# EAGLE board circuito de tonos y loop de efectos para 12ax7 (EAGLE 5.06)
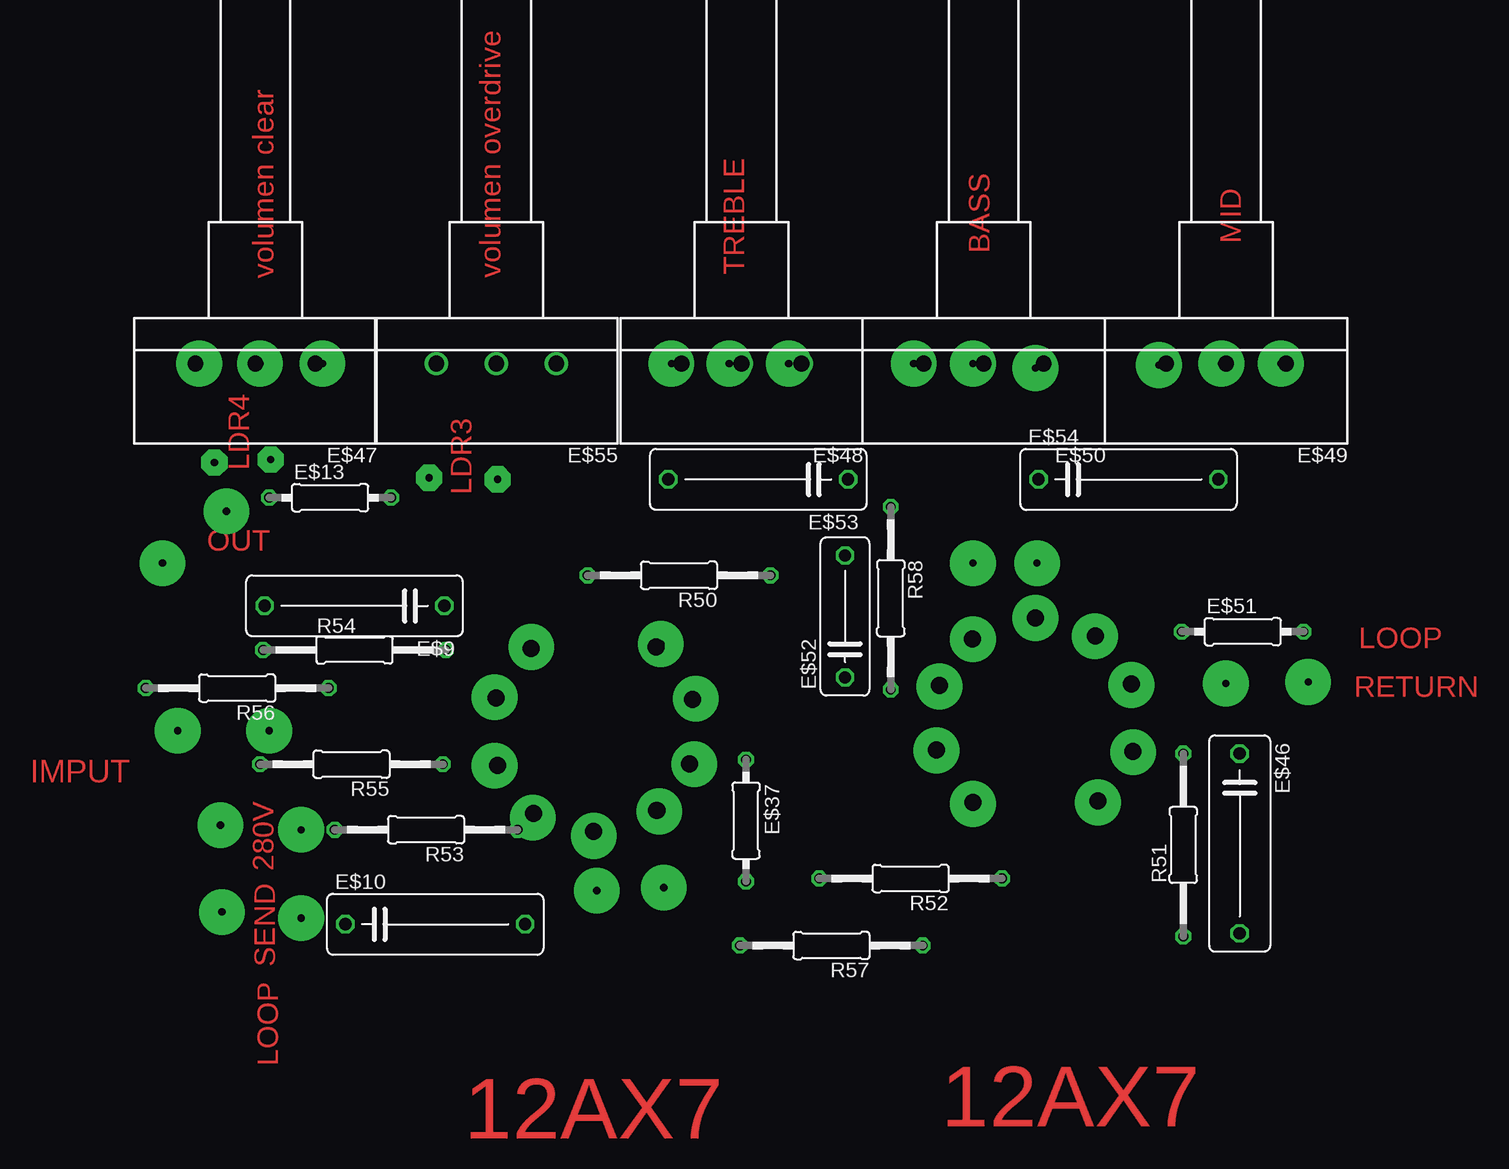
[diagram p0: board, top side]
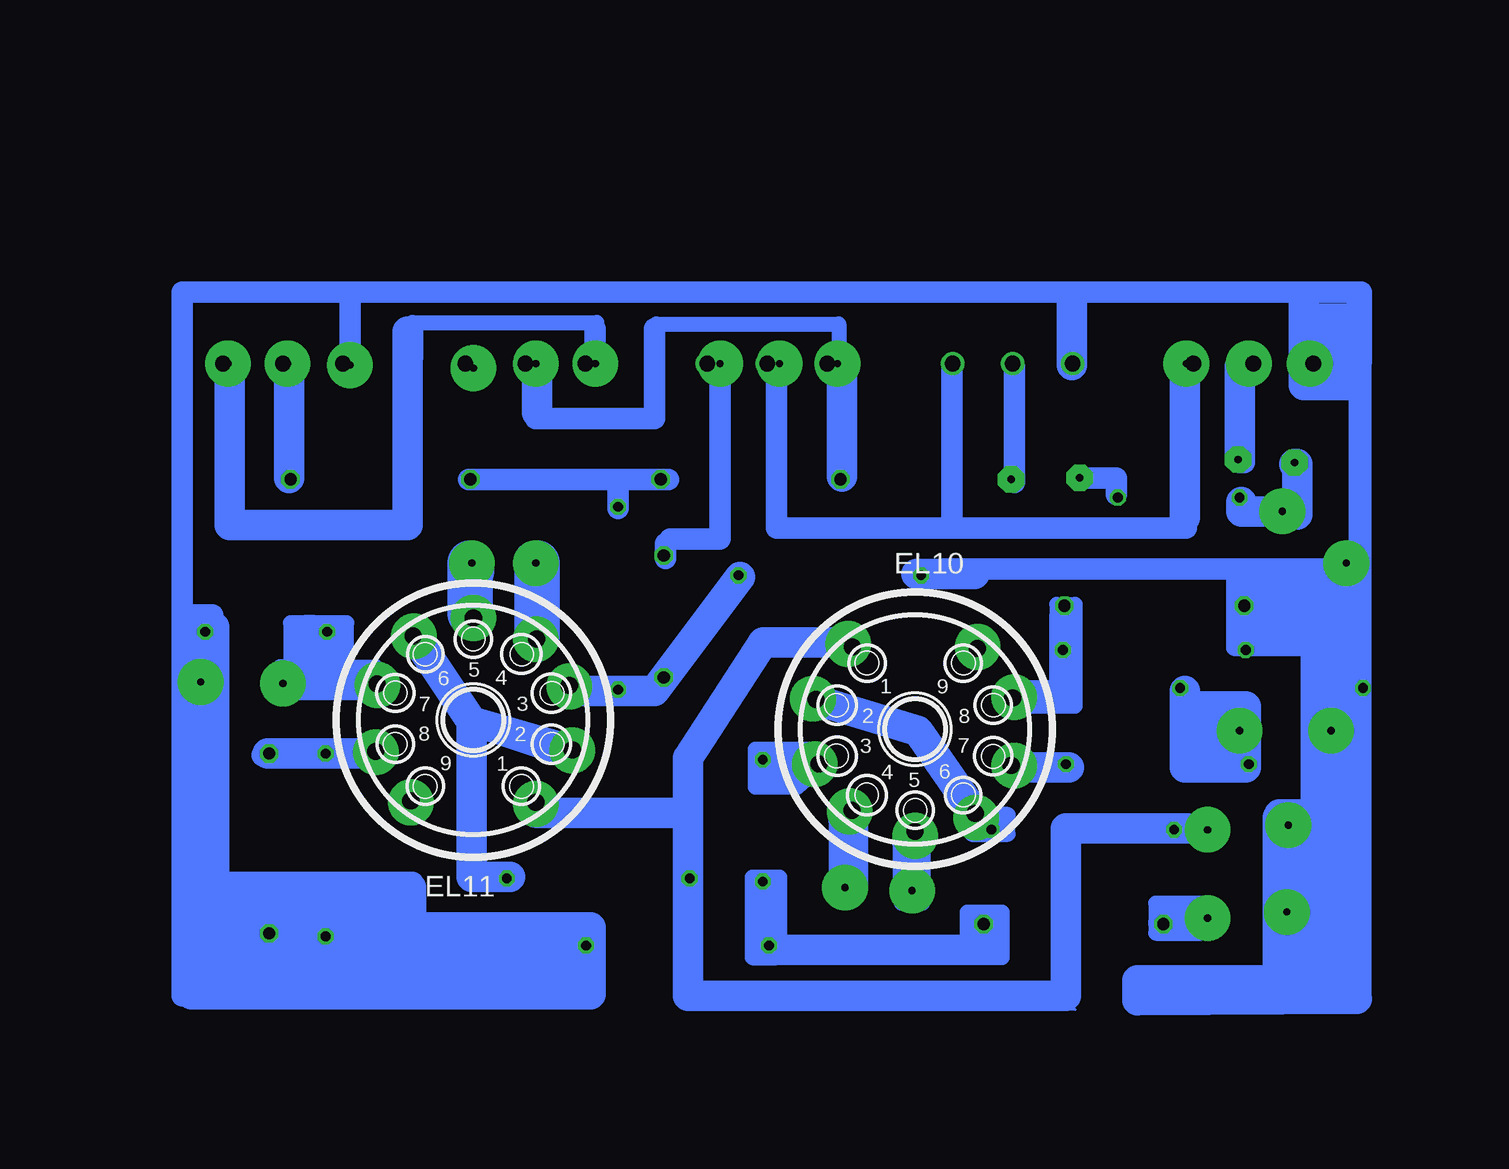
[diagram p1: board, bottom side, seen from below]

No outline drawn. Coordinates in mm, seen from the top.
Copper layers (1*16): Top 0.035mm / dielectric 1.5mm / Bottom 0.035mm
Design rules "default": minimum track width 10mil, minimum drill 24mil, track to track 8mil, track to pad 8mil, pad to pad 8mil, via to via 8mil, smd to smd 8mil, copper to edge 40mil, drill to drill 8mil, minimum pad ring 10mil, minimum via ring 8mil, stop-mask expansion 4mil, vias tented up to drill 0mil, thermal gap 10mil

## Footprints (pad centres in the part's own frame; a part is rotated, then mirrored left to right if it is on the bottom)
C150-054X183 = drill 1.016 octagon: 1 -7.493,0; 2 7.493,0
0207/10 = drill 0.813 octagon: 1 -5.08,0; 2 5.08,0
CIP20C-6MM = drill 1.3 pad 1.93 round: A -5,0; E 5,0; S 0,0
C102-043X133 = drill 1.016 octagon: 1 -5.08,0; 2 5.08,0
NOVAL = drill 1.422 pad 2.54 round: 1 5.207,-6.858; 2 8.254,-2.484; 3 8.004,2.893; 4 5.258,6.77; 5 0,8.524; 6 -5.004,7.024; 7 -8.004,3.02; 8 -8.127,-2.611; 9 -5.207,-6.731
0207/15 = drill 0.813 octagon: 1 -7.62,0; 2 7.62,0

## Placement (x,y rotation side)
E$9  1UF  [C150-054X183]  -92.84,-323.98 180 top
E$10  1UF  [C150-054X183]  -86.11,-350.52 0 top
E$13  PUENTE  [0207/10]  -94.87,-314.96 0 top
E$37  100K  [0207/10]  -60.2,-341.88 270 top
E$46  1UF  [C150-054X183]  -19.05,-343.79 270 top
E$47  1M  [CIP20C-6MM]  -101.09,-303.78 180 top
E$48  250K  [CIP20C-6MM]  -60.58,-303.78 180 top
E$49  25K  [CIP20C-6MM]  -20.19,-303.78 180 top
E$50  1M  [CIP20C-6MM]  -40.39,-303.78 180 top
E$51  1M  [0207/10]  -18.8,-326.14 0 top
E$52  470PF  [C102-043X133]  -51.94,-324.87 90 top
E$53  22NF  [C150-054X183]  -59.18,-313.44 180 top
E$54  22NF  [C150-054X183]  -28.32,-313.44 0 top
E$55  1M  [CIP20C-6MM]  -81.03,-303.78 180 top
EL10  [NOVAL]  -72.9,-334.26 180 bottom
EL11  [NOVAL]  -36.07,-333.5 0 bottom
R50  100K  [0207/15]  -65.79,-321.44 180 top
R51  2K2  [0207/15]  -23.75,-343.92 90 top
R52  220K  [0207/15]  -46.48,-346.71 180 top
R53  220K  [0207/15]  -86.87,-342.65 180 top
R54  1K8  [0207/15]  -92.84,-327.66 0 top
R55  220K  [0207/15]  -93.09,-337.19 180 top
R56  330K  [0207/15]  -102.62,-330.83 180 top
R57  2K2  [0207/15]  -53.09,-352.3 180 top
R58  47K  [0207/15]  -48.13,-323.34 270 top

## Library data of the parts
E$9 E$10 E$13 E$37 E$46 E$51-E$54 = rcl
E$47-E$50 E$55 = pot
EL10 EL11 = Tubes
R50-R58 = m-pad-2.1

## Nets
S$383: E$9.2

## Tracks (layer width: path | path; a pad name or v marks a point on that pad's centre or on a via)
S$1
  Bottom 1.778: -89.66,-314.71 -89.66,-313.31 -86.49,-313.31
S$2  (via drill 0.6 pad 3.81)
  Bottom 2.54: -41.4,-326.52 -41.27,-326.64
  Bottom 3.81: -41.4,-326.52 -41.4,-320.42 v-41.27,-320.42
S$3
  Bottom 2.54: -29.59,-352.17 -30.99,-352.17
S$4
  Bottom 2.54: -30.86,-347.47 -30.86,-350.01
S$9
  Bottom 2.54: -104.52,-312.17 -104.78,-312.17 -104.78,-316.36 -103,-316.36
S$10
  Bottom 2.54: -102.87,-316.1 -100.08,-316.1 -100.08,-315.34
S$11
  Bottom 2.54: -41.4,-303.78 -41.4,-307.85
S$12
  Bottom 2.54: -99.95,-304.04 -99.95,-311.66
S$13
  Bottom 0.406: -106.17,-298.96 -109.09,-298.96 -109.09,-298.7
S$164
  Bottom 1.676: -36.45,-320.68 -36.45,-324.99
S$334
  Bottom 2.54: -36.07,-325.12 -35.94,-325.12 -35.94,-324.99 -35.81,-324.87
S$335
  Bottom 2.54: -41.4,-320.8 -41.4,-326.9
S$336  (via drill 0.6 pad 3.81)
  other vias: -44.07,-330.71
S$337  (via drill 0.6 pad 3.81)
  other vias: -72.9,-343.15
S$338  (via drill 0.6 pad 3.81)
  other vias: -81.15,-337.31
S$339  (via drill 0.6 pad 3.81)
  other vias: -67.44,-341.12
S$340  (via drill 0.6 pad 3.81)
  other vias: -81.15,-331.6
S$341  (via drill 0.6 pad 3.81)
  other vias: -67.31,-327.15
S$342  (via drill 0.6 pad 3.81)
  other vias: -64.39,-331.72
S$343  (via drill 0.6 pad 3.81)
  other vias: -77.98,-341.63
S$344  (via drill 0.6 pad 3.81)
  other vias: -67.06,-347.47
S$345  (via drill 0.6 pad 3.81)
  other vias: -41.27,-340.49
S$346  (via drill 0.6 pad 3.81)
  Bottom 1.93: -36.07,-333.88 -36.07,-346.58 | -36.07,-333.88 -43.69,-336.42 | -30.99,-326.26 -31.24,-326.64 -36.07,-333.88
  Bottom 2.54: -35.94,-333.63 v-44.32,-336.04 | -31.24,-326.64 -35.94,-333.63 | -35.94,-333.63 -35.94,-346.58 -39.12,-346.58
S$347  (via drill 0.6 pad 3.81)
  other vias: -41.27,-326.77
S$348  (via drill 0.6 pad 3.81)
  other vias: -36.07,-324.99
S$349  (via drill 0.6 pad 3.81)
  other vias: -31.11,-326.52
S$350  (via drill 0.6 pad 3.81)
  other vias: -28.07,-330.58
S$351  (via drill 0.6 pad 3.81)
  other vias: -27.94,-336.17
S$352  (via drill 0.6 pad 3.81)
  Bottom 1.676: v-30.86,-340.36 -31.37,-340.36
S$353
  Bottom 1.93: -18.54,-336.42 -27.18,-336.42
S$354
  Bottom 1.93: -17.02,-351.66 -22.73,-351.66 | -22.73,-351.66 -23.37,-351.66 | -17.02,-351.66 -17.02,-354.2 -14.48,-354.2 | -17.02,-351.66 -13.21,-351.66 -13.21,-352.93 -15.75,-352.93 | -22.73,-351.66 -25.4,-351.66 -25.27,-356.62
S$355
  Bottom 1.93: -13.21,-347.09 -30.99,-347.09
S$356  (via drill 0.6 pad 3.81)
  other vias: -78.11,-327.41
S$357
  Bottom 2.54: -12.57,-325.25 -12.57,-355.22 | -45.85,-350.77 -45.85,-356.36 -12.57,-356.36 -12.57,-355.22 | -12.57,-355.22 -12.57,-354.08 -43.94,-354.08 -43.94,-352.68 -43.81,-352.68 -43.81,-352.3 -15.62,-352.3
S$358  (via drill 0.6 pad 3.81)
  other vias: -97.28,-342.65
S$359  (via drill 0.6 pad 3.81)
  other vias: -20.19,-330.45
S$360  (via drill 0.6 pad 3.81)
  other vias: -13.34,-330.33
S$361
  Bottom 2.54: -81.03,-337.44 -85.72,-337.44
S$362
  Bottom 2.54: -72.77,-343.03 -72.77,-347.6
S$363
  Bottom 2.54: -67.31,-341.12 -67.31,-347.47
S$366
  Bottom 2.54: -18.92,-336.3 -27.94,-336.3
S$367
  Bottom 2.54: -13.72,-349.12 -30.61,-349.12
S$368  (via drill 0.6 pad 3.81)
  other vias: -35.94,-320.42
S$369
  Bottom 3.81: -35.81,-324.61 -35.81,-320.42 -35.94,-321.06
S$370  (via drill 0.6 pad 3.81)
  other vias: -72.64,-347.73
S$371  (via drill 0.6 pad 3.81)
  other vias: -64.52,-337.19
S$372  (via drill 0.6 pad 3.81)
  other vias: -97.28,-350.01
S$373
  Bottom 2.54: -78.61,-350.39 -78.49,-352.68 -60.45,-352.68 -60.45,-347.35
S$374
  Bottom 2.54: -95.63,-342.52 -85.47,-342.52 -85.47,-356.49 -53.98,-356.49 -53.98,-341.25
S$375
  Bottom 2.54: -64.52,-336.93 -60.33,-336.93 -60.33,-338.45
S$376
  Bottom 1.93: -41.15,-340.23 -41.15,-341.5
S$377
  Bottom 2.54: -41.4,-341.25 -53.47,-341.25
S$378
  Bottom 2.54: -45.59,-350.77 -13.34,-350.77 -13.34,-350.65
S$379
  Bottom 2.54: -93.6,-350.39 -97.28,-350.14
S$380
  Bottom 2.54: -77.98,-341.38 -73.15,-334.39 -63.88,-331.6
S$381
  Bottom 2.54: -97.92,-334.77 -97.92,-337.19
S$382
  Bottom 2.54: -85.34,-324.87 -85.34,-331.6 -81.03,-331.6
S$383
  Bottom 2.54: -100.58,-326.26 -100.58,-322.71 E$9.2 -100.33,-325.12 -109.35,-325.12
S$384
  Bottom 1.778: -52.07,-318.77 -52.07,-320.04
S$385
  Bottom 2.54: -67.31,-327.02 -60.2,-327.02 -53.98,-336.68 -53.98,-344.68
S$386
  Bottom 2.54: -44.07,-331.34 -43.94,-331.22
S$387
  Bottom 2.54: -28.19,-330.58 -23.37,-330.45 -20.07,-330.45
S$388
  Bottom 1.93: -109.98,-303.28 -109.98,-356.74
S$389
  Bottom 2.54: -103.12,-341.63 -103.12,-356.49
S$390
  Bottom 2.54: -103.25,-341.38 -109.35,-341.38
S$391
  Bottom 2.54: -106.3,-326.77 -109.47,-326.77 | -100.46,-326.77 -106.3,-326.77 | -109.22,-356.36 -103.25,-356.36 -103.25,-356.49 -104.9,-356.49 -104.9,-342.65 -106.68,-342.65 | -106.68,-342.65 -108.2,-342.65 -108.2,-342.9 -108.08,-342.9 -108.08,-354.84 -106.55,-354.84 | -106.55,-354.84 -106.17,-354.84 | -106.55,-354.84 -106.55,-344.3 | -106.3,-326.77 -106.3,-342.65 -106.68,-342.65
S$392
  Bottom 0.254: -109.35,-356.87 -109.35,-357.63
S$393
  Bottom 0.254: -86.23,-357.63 -85.6,-357.63
S$394
  Bottom 2.54: -109.73,-356.74 -91.44,-356.87 -91.44,-355.22 -101.98,-355.22
S$395
  Bottom 2.54: -108.33,-327.28 -108.33,-342.77 -108.58,-342.77
S$396
  Bottom 2.54: -14.48,-325.75 -14.48,-353.19 -13.84,-353.19
S$397
  Bottom 2.54: -73.03,-321.31 -77.85,-321.31
S$398
  Bottom 1.778: -25.78,-297.81 -11.81,-297.81 -11.81,-324.74 | -25.78,-297.81 -110.11,-297.81 -110.11,-303.66 -105.79,-303.66 | -11.81,-324.74 -11.81,-356.49 | -25.78,-297.81 -25.78,-304.42 | -11.81,-324.74 -14.35,-324.74
S$399
  Bottom 1.778: -23.24,-326.01 -24.51,-326.01 -24.51,-329.82
S$400
  Bottom 1.778: -100.84,-303.78 -100.33,-303.78 -100.33,-312.04
S$401
  Bottom 1.778: -95.63,-303.78 -95.63,-303.91 -95.5,-317.5 -61.34,-317.5 -61.34,-303.78
  Bottom 2.54: -95.63,-303.91 -95.38,-303.91 -95.38,-316.61
S$402
  Bottom 1.778: -58.04,-321.44 -52.83,-329.18
S$404
  Bottom 1.778: -35.69,-313.44 -52.32,-313.44
S$405
  Bottom 1.778: -100.71,-323.47 -100.71,-320.93 -99.44,-320.93 | -75.31,-320.93 -99.44,-320.93 | -99.44,-320.93 -108.33,-320.93 -108.33,-322.2 | -108.33,-322.2 -108.33,-323.47 | -108.33,-322.2 -101.98,-322.2 -101.98,-323.47 -107.06,-323.47
S$406
  Bottom 1.778: -67.06,-304.04 -66.42,-304.04
  Bottom 2.54: -66.8,-313.18 -66.8,-304.17 -67.06,-304.04 -66.29,-304.04
S$407
  Bottom 1.778: -20.7,-304.42 -20.7,-313.31 -20.7,-313.44
  Bottom 2.54: -20.7,-303.91 -20.7,-313.31
S$408  (via drill 0.6 pad 3.81)
  other vias: -103.5,-316.1
S$409  (via drill 0.6 pad 3.81)
  other vias: -104.01,-342.26
S$410
  Bottom 1.778: -51.18,-300.86 -51.18,-308.36 -41.27,-308.36
S$411
  Bottom 1.27: -66.55,-303.66 -66.55,-300.48 -51.31,-300.48
S$412
  Bottom 1.778: -30.99,-300.74 -30.86,-317.12 -15.62,-317.12 -15.62,-303.78 -15.62,-303.15
  Bottom 2.54: -15.62,-303.78 -15.75,-303.78 -15.75,-317.25 -30.61,-317.25 -30.61,-301.12
S$413
  Bottom 1.778: -46.23,-300.86 -46.23,-303.4
S$414
  Bottom 1.27: -30.99,-300.36 -46.35,-300.36
S$415
  Bottom 1.27: -99.44,-321.31 -99.44,-327.53 -105.41,-327.53
S$416
  Bottom 1.27: -96.77,-349.12 -96.77,-351.28 -92.96,-351.28 -92.96,-348.74 -97.54,-348.74
S$417
  Bottom 1.27: -77.22,-352.55 -77.22,-349.5 -80.14,-349.5 -80.14,-353.31 -75.69,-353.31
S$418
  Bottom 1.27: -61.59,-351.92 -61.59,-346.58 -59.31,-346.58 -59.31,-353.31 -61.34,-353.31
S$419
  Bottom 1.27: -64.77,-335.92 -59.56,-335.92 -59.56,-339.09 -63.12,-339.09 -65.15,-337.31 -61.85,-338.2
S$420
  Bottom 1.27: -68.33,-347.47 -68.33,-341.88 -66.29,-341.88 -66.29,-347.6
S$421
  Bottom 1.27: -71.75,-348.74 -73.53,-348.74 -73.53,-343.79 -71.63,-343.79 -71.63,-348.23
S$422
  Bottom 1.27: -25.53,-329.06 -27.94,-329.06 | -20.83,-329.06 -25.53,-329.06 | -20.83,-329.06 -19.94,-329.06 -19.94,-331.22 -27.18,-331.22 -27.18,-331.09 | -25.53,-329.06 -25.53,-325.37 -22.86,-325.37 | -22.86,-325.37 -21.97,-325.37 -21.97,-329.69 -21.84,-329.69 -21.84,-327.02 -23.11,-327.02 -23.11,-328.42 | -22.86,-325.37 -20.83,-325.37 -20.83,-329.06
S$423
  Bottom 1.778: -48.13,-313.69 -48.13,-315.85
S$424
  Bottom 1.778: -75.95,-303.78 -75.95,-316.87
S$426
  Bottom 2.54: -105.28,-298.45 -105.28,-302.13 | -105.28,-302.13 -105.28,-304.04 -109.35,-304.04 -109.35,-300.1 -106.68,-300.1 -106.68,-302.01 -107.57,-302.01 | -109.47,-305.56 -105.28,-305.56 -105.28,-302.13
S$427
  Bottom 1.27: -78.36,-341.25 -78.36,-341.38 -80.64,-341.38 -80.64,-343.03 -77.6,-343.03 -77.6,-342.14 -80.01,-342.14 -80.01,-341.88 -77.6,-341.88
S$428
  Bottom 1.27: -81.66,-330.58 -81.66,-330.83 -84.71,-330.83 -84.71,-323.85 -86.23,-323.85 -86.23,-332.36 -82.17,-332.36
S$429
  Bottom 1.27: -98.3,-336.55 -98.3,-337.82
S$430
  Bottom 2.54: -95.38,-333.63 -95.38,-332.36 -100.46,-332.36 -100.46,-337.44 -95.38,-337.44 -95.38,-333.63 | -95.38,-331.09 -95.38,-333.63
S$431
  Bottom 2.54: -96.65,-333.63 -99.19,-333.63
S$432  (via drill 0.6 pad 3.81)
  other vias: -103.89,-349.5
S$433  (via drill 0.6 pad 3.81)
  other vias: -108.84,-320.42
S$434  (via drill 0.6 pad 3.81)
  other vias: -107.57,-334.39
S$435  (via drill 0.6 pad 3.81)
  other vias: -99.95,-334.39
S$436  (via drill 0.6 pad 3.81)
  other vias: -95.5,-303.78
S$437  (via drill 0.6 pad 3.81)
  other vias: -105.79,-303.78
S$438  (via drill 0.6 pad 3.81)
  other vias: -100.71,-303.78
S$439  (via drill 0.6 pad 3.81)
  other vias: -56.64,-303.78
S$440  (via drill 0.6 pad 3.81)
  other vias: -66.42,-303.78
S$441  (via drill 0.6 pad 3.81)
  other vias: -61.59,-303.78
S$442  (via drill 0.6 pad 3.81)
  other vias: -46.23,-303.78
S$443  (via drill 0.6 pad 3.81)
  other vias: -41.27,-303.78
S$444  (via drill 0.6 pad 3.81)
  other vias: -36.07,-304.17
S$445  (via drill 0.6 pad 3.81)
  other vias: -15.62,-303.78
S$446  (via drill 0.6 pad 3.81)
  other vias: -25.78,-303.91
S$447  (via drill 0.6 pad 3.81)
  other vias: -20.57,-303.78
S$448
  Bottom 1.778: -56.64,-303.91 -56.64,-310.26
S$449  (via drill 0.6 pad 2.18)
  other vias: -80.9,-313.44
S$450  (via drill 0.6 pad 2.18)
  other vias: -86.61,-313.31
S$451
  Bottom 1.778: -81.15,-304.04 -81.15,-313.69
S$452
  Bottom 1.778: -85.98,-298.58 -85.98,-298.7
  Bottom 2.54: -85.98,-303.91 -85.98,-298.7
S$453  (via drill 0.6 pad 2.18)
  other vias: -99.82,-311.79
S$454  (via drill 0.6 pad 2.18)
  other vias: -104.52,-312.04
S$455
  Bottom 2.54: -58.29,-321.56 -51.18,-331.09 -44.2,-331.09 -44.2,-331.22
S$457
  Bottom 1.778: -56.64,-310.39 -56.64,-318.39 -52.45,-318.39

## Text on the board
Top: volumen overdrive | volumen clear | TREBLE | BASS | MID | LDR4 | LDR3 | OUT | LOOP | RETURN | IMPUT | 280V | SEND | LOOP | 12AX7 | 12AX7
